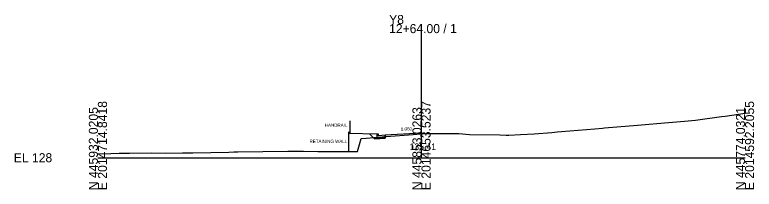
# Model space of a CAD drawing. Extents: x -26 to 1403, y -10 to 8043.
# Drawn here: x 1174.3 to 1402.8, y -9.7 to 44.1 of the extents above; entities that cross this region are included whole.
import ezdxf

# ---------------------------------------------------------------- set-up
doc = ezdxf.new("R2010")
doc.units = 0
for name, color, linetype in [('Exist Cross Section Cell', 7, 'Continuous'), ('Exist XS Center Line Elevation Label', 7, 'Continuous'), ('Exist XS Ground Line', 7, 'Continuous'), ('Prop CMT Conc Surface', 7, 'Continuous'), ('Prop CMT Concrete Structures', 7, 'Continuous'), ('Prop CMT Pvmt Course 1', 7, 'Continuous'), ('Prop CMT Pvmt Course 1 CG', 7, 'Continuous'), ('Prop CMT Pvmt Course 2', 7, 'Continuous'), ('Prop CMT Pvmt Course 3', 7, 'Continuous'), ('Prop CMT Pvmt Surface', 7, 'Continuous'), ('Prop CMT Pvmt Wedge Surface 1', 7, 'Continuous'), ('Prop CMT Pvmt Wedge Surface 2', 7, 'Continuous'), ('Prop CMT Pvmt Wedge Surface 3', 7, 'Continuous'), ('Prop CMT Slope Grass', 7, 'Continuous'), ('Prop CMT Subgrade Earthwork', 7, 'Continuous'), ('Prop XS Hydro Elevations', 7, 'Continuous'), ('Prop XS Retaining Wall', 7, 'Continuous'), ('Prop XS SE Text', 7, 'Continuous'), ('Prop XS Vertical Lines', 7, 'Continuous')]:
    doc.layers.add(name, color=color, linetype=linetype)

msp = doc.modelspace()

# ---------------------------------------------------------------- linework, layer by layer
at = {"layer": 'Exist Cross Section Cell'}
for p, q in [((1300, 0), (1300, 41.23)), ((1200, 0), (1300, 0)), ((1300, 0), (1400, 0))]:
    msp.add_line(p, q, dxfattribs=at)
at = {"layer": 'Exist XS Ground Line'}
msp.add_lwpolyline([(1200, 1.21), (1204, 1.31), (1206.53, 1.4), (1209.8, 1.45), (1216.66, 1.47), (1220.79, 1.46), (1226.11, 1.49), (1227.92, 1.5), (1229.32, 1.51), (1240.45, 1.76), (1241.98, 1.79), (1243.21, 1.8), (1258.73, 2.01), (1263.55, 2.03), (1267.96, 1.97), (1268.58, 1.94), (1277.03, 1.97), (1280.24, 1.97), (1280.82, 4.13), (1281.32, 5.92), (1282.91, 6.02), (1289.1, 6.54), (1297.47, 7.21), (1299.71, 7.4), (1301.56, 7.44), (1308.15, 7.5), (1308.93, 7.43), (1311.56, 7.44), (1314.89, 7.14), (1324.18, 7.08), (1326.2, 6.97), (1327.01, 6.96), (1330.6, 7.14), (1334.83, 7.34), (1340.28, 7.78), (1341.96, 7.94), (1343.26, 8.06), (1353.61, 8.95), (1355.92, 9.15), (1356.59, 9.2), (1366.79, 10.04), (1376.38, 10.82), (1381.25, 11.31), (1384.73, 11.61), (1392.74, 12.71), (1393.9, 12.82), (1400, 13.74)], dxfattribs=at)
at = {"layer": 'Prop CMT Conc Surface'}
for points in [[(1286.75, 6.75), (1286.75, 7.25), (1286.25, 7.25)], [(1288.75, 6.95), (1286.75, 6.75)]]:
    msp.add_lwpolyline(points, dxfattribs=at)
at = {"layer": 'Prop CMT Concrete Structures'}
for points in [[(1288.75, 6.95), (1286.75, 6.75), (1286.75, 7.25), (1286.25, 7.25)], [(1286.25, 7.25), (1286.25, 6.22), (1288.75, 6.37)], [(1288.75, 6.37), (1288.75, 6.95)]]:
    msp.add_lwpolyline(points, dxfattribs=at)
at = {"layer": 'Prop CMT Pvmt Course 1'}
for points in [[(1300, 7.63), (1288.75, 6.95)], [(1288.75, 6.95), (1288.75, 6.7)], [(1288.75, 6.95), (1288.75, 6.7)]]:
    msp.add_lwpolyline(points, dxfattribs=at)
at = {"layer": 'Prop CMT Pvmt Course 1 CG'}
for points in [[(1288.75, 6.37), (1285.75, 6.19), (1285.44, 5.88)], [(1285.44, 5.88), (1288.75, 6.08)], [(1288.75, 6.08), (1288.75, 6.37)]]:
    msp.add_lwpolyline(points, dxfattribs=at)
at = {"layer": 'Prop CMT Pvmt Course 2'}
msp.add_lwpolyline([(1288.75, 6.7), (1288.75, 6.45)], dxfattribs=at)
msp.add_lwpolyline([(1288.75, 6.7), (1288.75, 6.45)], dxfattribs=at)
at = {"layer": 'Prop CMT Pvmt Course 3'}
msp.add_lwpolyline([(1288.75, 6.45), (1288.75, 6.08)], dxfattribs=at)
msp.add_lwpolyline([(1288.75, 6.45), (1288.75, 6.08)], dxfattribs=at)
at = {"layer": 'Prop CMT Pvmt Surface'}
msp.add_lwpolyline([(1300, 7.63), (1288.75, 6.95)], dxfattribs=at)
at = {"layer": 'Prop CMT Pvmt Wedge Surface 1'}
msp.add_lwpolyline([(1288.75, 6.7), (1288.75, 6.95)], dxfattribs=at)
msp.add_lwpolyline([(1288.75, 6.7), (1288.75, 6.95)], dxfattribs=at)
at = {"layer": 'Prop CMT Pvmt Wedge Surface 2'}
msp.add_lwpolyline([(1288.75, 6.7), (1288.75, 6.95)], dxfattribs=at)
msp.add_lwpolyline([(1288.75, 6.7), (1288.75, 6.95)], dxfattribs=at)
at = {"layer": 'Prop CMT Pvmt Wedge Surface 3'}
msp.add_lwpolyline([(1288.75, 6.45), (1288.75, 6.95)], dxfattribs=at)
msp.add_lwpolyline([(1288.75, 6.45), (1288.75, 6.95)], dxfattribs=at)
at = {"layer": 'Prop CMT Slope Grass'}
msp.add_lwpolyline([(1286.25, 7.25), (1277.43, 7.43)], dxfattribs=at)
at = {"layer": 'Prop CMT Subgrade Earthwork'}
msp.add_line((1277.43, 7.43), (1277.43, 1.97), dxfattribs=at)
msp.add_lwpolyline([(1288.75, 6.08), (1285.44, 5.88), (1284.03, 7.3)], dxfattribs=at)
at = {"layer": 'Prop XS Retaining Wall'}
msp.add_line((1277.43, 7.98), (1277.43, 1.97), dxfattribs=at)
at = {"layer": 'Prop XS Vertical Lines'}
msp.add_line((1277.93, 7.42), (1277.93, 11.42), dxfattribs=at)

# ---------------------------------------------------------------- texts
at = {"layer": 'Exist Cross Section Cell'}
for s, p in [('Y8', (1290, 41.23)), ('12+64.00 / 1', (1290, 38.43)), ('EL 128', (1174, -1.4))]:
    msp.add_text(s, height=2.8, dxfattribs=at).set_placement(p)
for s, p in [('E 2014714.8418', (1202.8, -10)), ('E 2014653.5237', (1302.8, -10)), ('E 2014592.2055', (1402.8, -10)), ('N 445932.0205', (1200, -10)), ('N 445853.0263', (1300, -10)), ('N 445774.0321', (1400, -10))]:
    msp.add_text(s, height=2.8, rotation=90, dxfattribs=at).set_placement(p)
at = {"layer": 'Exist XS Center Line Elevation Label'}
msp.add_text('135.41', height=2, dxfattribs=at).set_placement((1296.32, 2.41))
at = {"layer": 'Prop XS Hydro Elevations'}
for s, p in [('HANDRAIL', (1270.12, 9.54)), ('RETAINING WALL', (1265.41, 4.55))]:
    msp.add_text(s, height=1, dxfattribs=at).set_placement(p)
at = {"layer": 'Prop XS SE Text'}
msp.add_text('0.060', height=1, rotation=3.4336, dxfattribs=at).set_placement((1293.65, 8.25))

doc.saveas('drawing.dxf')
